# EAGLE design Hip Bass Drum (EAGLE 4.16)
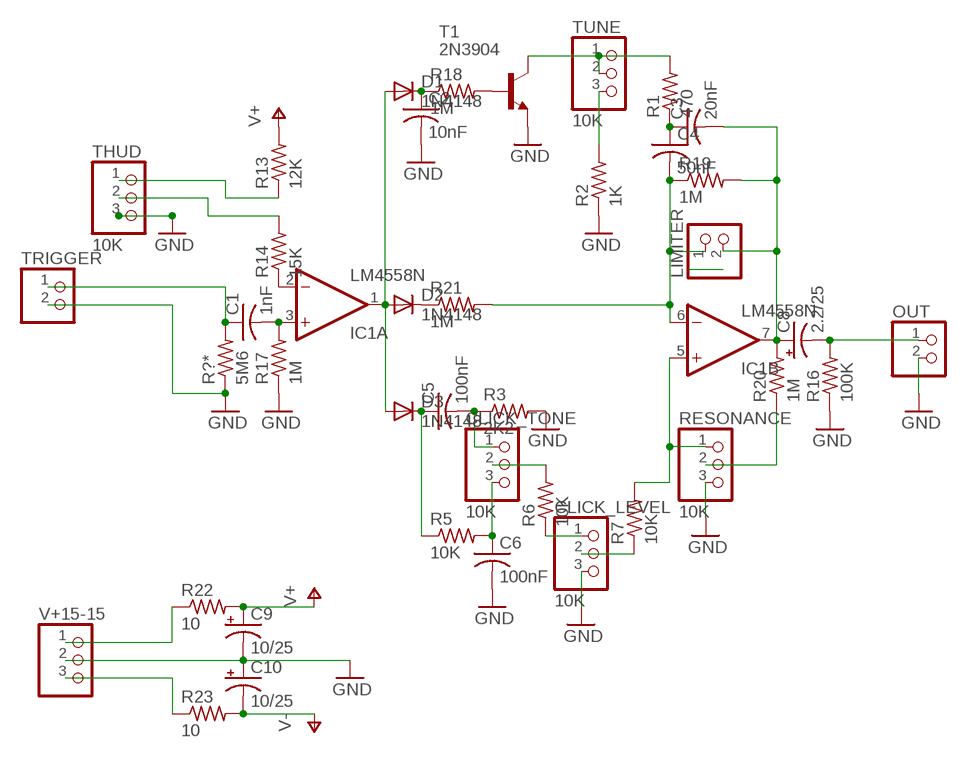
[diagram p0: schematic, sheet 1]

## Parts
C1  1nF  C-US025-030X050  [C025-030X050]
C2  10nF  C-US025-030X050  [C025-030X050]
C3  20nF  C-US025-030X050  [C025-030X050]
C4  50nF  C-US025-030X050  [C025-030X050]
C5  100nF  C-US025-030X050  [C025-030X050]
C6  100nF  C-US025-030X050  [C025-030X050]
C8  2.2/25  CPOL-USE2.5-7  [E2,5-7]
C9  10/25  CPOL-USE2.5-7  [E2,5-7]
C10  10/25  CPOL-USE2.5-7  [E2,5-7]
CLICK_LEVEL  10K  PINHD-1X3  [1X03]
CLICK_TONE  10K  PINHD-1X3  [1X03]
D1  1N4148  [DO35-10]
D2  1N4148  [DO35-10]
D3  1N4148  [DO35-10]
IC1  LM4558N  [DIL08]
LIMITER  PINHD-1X2  [1X02]
OUT  PINHD-1X2  [1X02]
R1  470  R-US_0207/10  [0207/10]
R2  1K  R-US_0207/10  [0207/10]
R3  2K2  R-US_0207/10  [0207/10]
R5  10K  R-US_0207/10  [0207/10]
R6  10K  R-US_0207/10  [0207/10]
R7  10K  R-US_0207/10  [0207/10]
R13  12K  R-US_0207/10  [0207/10]
R14  15K  R-US_0207/10  [0207/10]
R16  100K  R-US_0207/10  [0207/10]
R17  1M  R-US_0207/10  [0207/10]
R18  1M  R-US_0207/10  [0207/10]
R19  1M  R-US_0207/10  [0207/10]
R20  1M  R-US_0207/10  [0207/10]
R21  1M  R-US_0207/10  [0207/10]
R22  10  R-US_0207/10  [0207/10]
R23  10  R-US_0207/10  [0207/10]
R?*  5M6  R-US_0207/10  [0207/10]
RESONANCE  10K  PINHD-1X3  [1X03]
T1  2N3904  [TO92]
THUD  10K  PINHD-1X3  [1X03]
TRIGGER  PINHD-1X2  [1X02]
TUNE  10K  PINHD-1X3  [1X03]
V+15-15  PINHD-1X3  [1X03]

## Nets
GND: C2.2 C6.2 C9.- C10.+ CLICK_LEVEL.3 OUT.2 R2.1 R3.2 R16.1 R17.1 R?*.1 RESONANCE.3 T1.3(E) THUD.3 TRIGGER.2 V+15-15.2
N$1: C1.2 IC1.3(A:+IN) R17.2
N$2: C1.1 R?*.2 TRIGGER.1
N$3: IC1.2(A:-IN) R14.1
N$4: R22.1 V+15-15.1
N$5: R23.1 V+15-15.3
N$6: R13.1 THUD.1
N$7: R14.2 THUD.2
N$8: C2.1 D1.C R18.1
N$9: R18.2 T1.2(B)
N$10: D1.A D2.A D3.A IC1.1(A:OUT)
N$11: R1.2 T1.1(C) TUNE.1 TUNE.2
N$12: R2.2 TUNE.3
N$13: C3.1 C4.1 R1.1
N$14: C4.2 IC1.6(B:-IN) LIMITER.1 R19.1 R21.2
N$15: C3.2 C8.+ IC1.7(B:OUT) LIMITER.2 R19.2 R20.2
N$16: D2.C R21.1
N$17: C8.- OUT.1 R16.2
N$18: IC1.5(B:+IN) R7.2 RESONANCE.1
N$19: R20.1 RESONANCE.2
N$20: C5.1 D3.C R5.1
N$21: C6.1 CLICK_TONE.3 R5.2
N$22: C5.2 CLICK_TONE.1 R3.1
N$23: CLICK_TONE.2 R6.2
N$24: CLICK_LEVEL.1 R6.1
N$25: CLICK_LEVEL.2 R7.1
V+: C9.+ R13.2 R22.2
V-: C10.- R23.2

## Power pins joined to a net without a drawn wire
V+: IC1.8(P:V+)
V-: IC1.4(P:V-)

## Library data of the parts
C1-C6 = rcl:C-US: CAPACITOR, American symbol
C8-C10 = rcl:CPOL-US: POLARIZED CAPACITOR, American symbol
CLICK_LEVEL CLICK_TONE RESONANCE THUD TUNE V+15-15 = pinhead:PINHD-1X3: PIN HEADER
D1-D3 = diode:1N4148: DIODE
IC1 = linear:*4558: OP AMP
LIMITER OUT TRIGGER = pinhead:PINHD-1X2: PIN HEADER
R1-R3 R5-R7 R13 R14 R16-R23 R?* = rcl:R-US_: RESISTOR, American symbol
T1 = transistor:2N3904: NPN TRANSISTOR

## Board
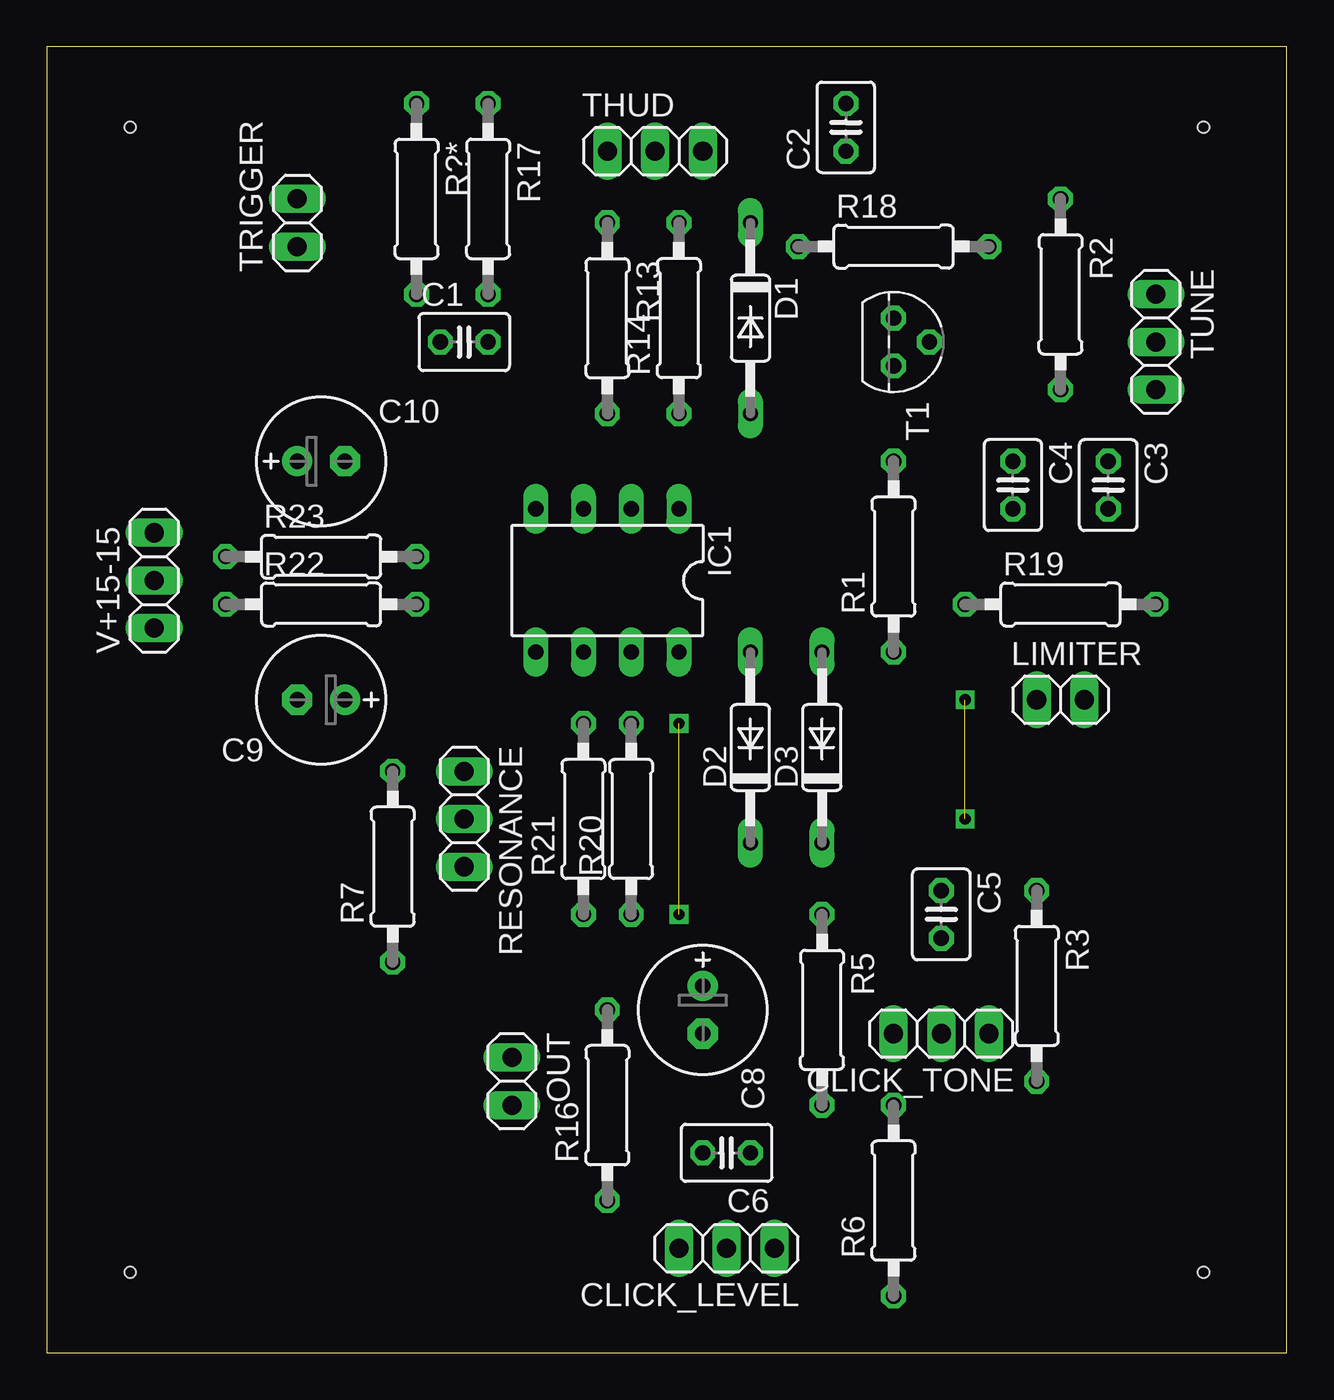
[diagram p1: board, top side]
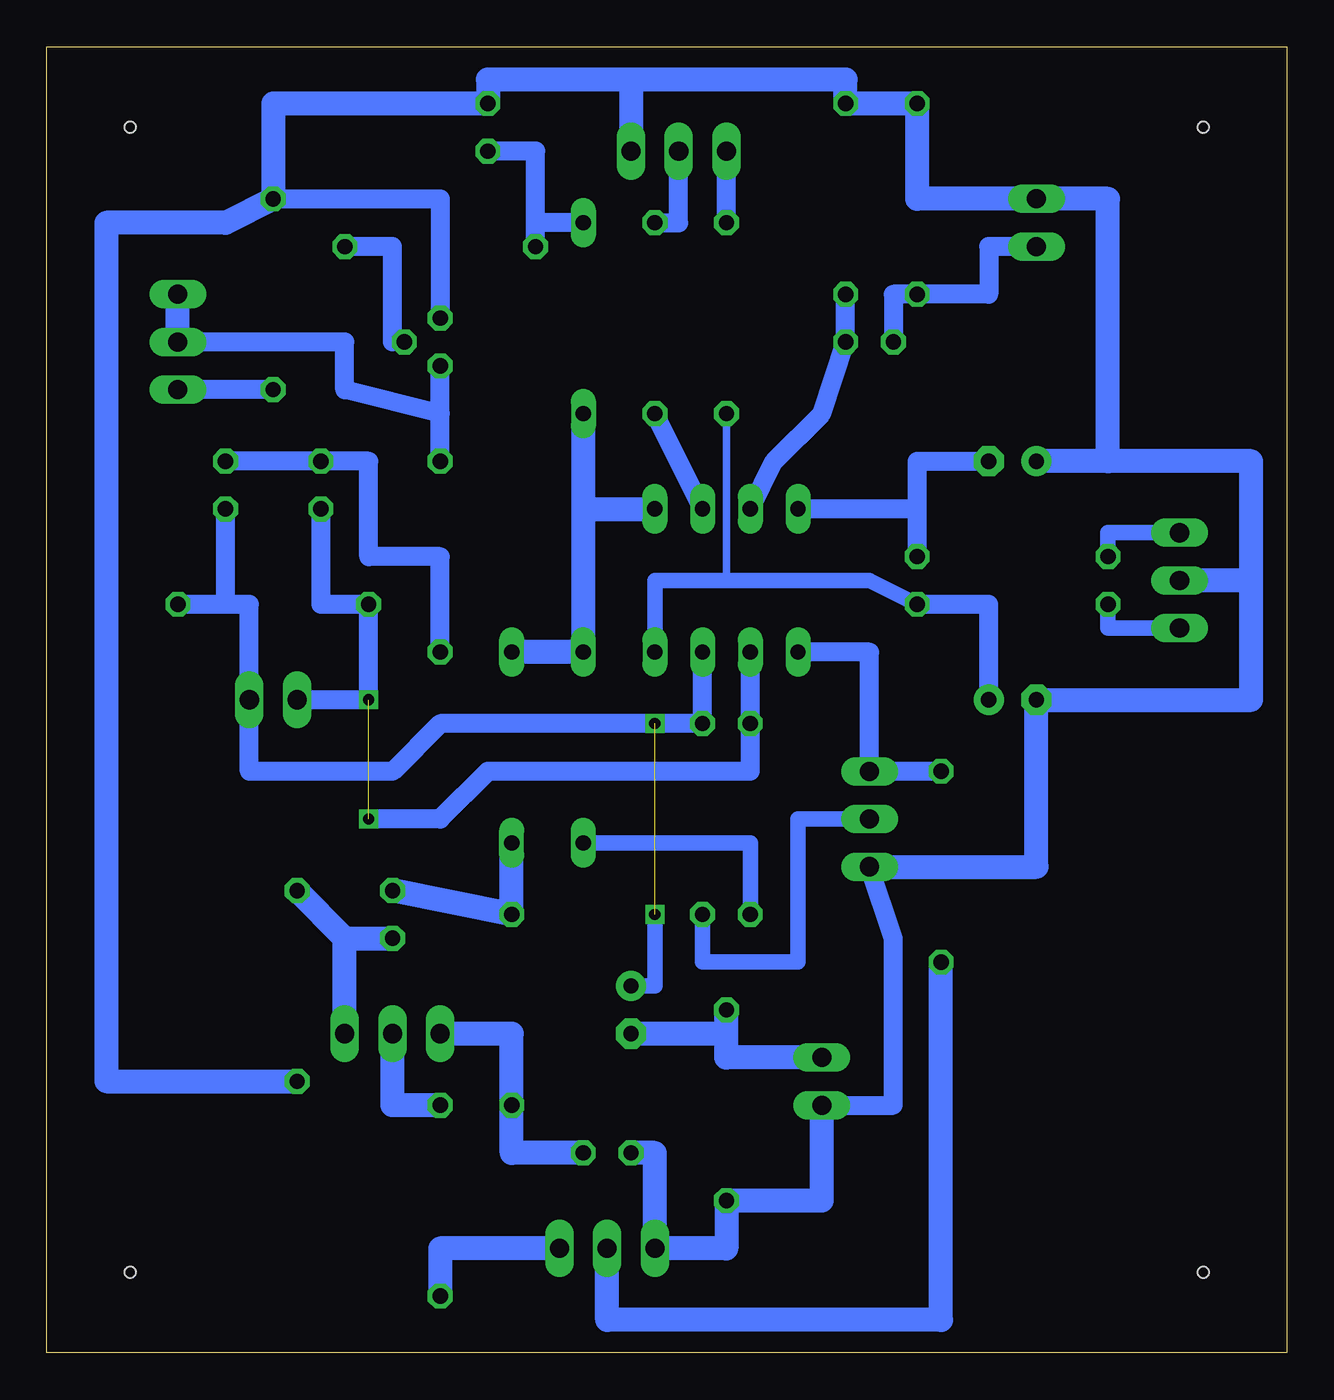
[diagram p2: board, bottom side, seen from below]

Size 66.02 x 69.52 mm. Coordinates in mm from the lower left corner, seen from the top.
Outline: 0,0 66.02,0 66.02,69.52 0,69.52 0,0
Copper layers (1*16): Top 0.035mm / dielectric 1.5mm / Bottom 0.035mm
Design rules "default": minimum track width 10mil, minimum drill 24mil, track to track 8mil, track to pad 8mil, pad to pad 8mil, via to via 8mil, smd to smd 8mil, copper to edge 40mil, drill to drill 8mil, minimum pad ring 10mil, minimum via ring 8mil, stop-mask expansion 4mil, vias tented up to drill 0mil, thermal gap 10mil
Holes 0.6 mm at 4.44,4.28 4.44,65.24 61.59,65.24 61.59,4.28

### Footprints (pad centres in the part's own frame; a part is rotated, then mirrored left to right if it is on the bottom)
C025-030X050 = drill 0.813 octagon: 1 -1.27,0; 2 1.27,0
E2,5-7 = drill 0.813 pad 1.6 round: + -1.27,0 | drill 0.813 pad 1.6 octagon: - 1.27,0
1X03 = drill 1.016 long: 1 -2.54,0; 2 0,0; 3 2.54,0
DO35-10 = drill 0.813 long: A 5.08,0; C -5.08,0
DIL08 = drill 0.813 long: 1 -3.81,-3.81; 2 -1.27,-3.81; 3 1.27,-3.81; 4 3.81,-3.81; 5 3.81,3.81; 6 1.27,3.81; 7 -1.27,3.81; 8 -3.81,3.81
1X02 = drill 1.016 long: 1 -1.27,0; 2 1.27,0
0207/10 = drill 0.813 octagon: 1 -5.08,0; 2 5.08,0
TO92 = drill 0.813 octagon: 1 1.27,0; 2 0,1.905; 3 -1.27,0

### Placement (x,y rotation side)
C1  22.22,53.81 0 top
C2  42.54,65.24 90 top
C3  56.51,46.19 270 top
C4  51.43,46.19 270 top
C5  47.62,23.33 270 top
C6  36.19,10.63 180 top
C8  34.92,18.25 270 top
C9  14.6,34.76 180 top
C10  14.6,47.46 0 top
CLICK_LEVEL  36.19,5.55 180 top
CLICK_TONE  47.62,16.98 180 top
D1  37.46,55.08 270 top
D2  37.46,32.22 90 top
D3  41.27,32.22 90 top
IC1  29.84,41.11 180 top
LIMITER  53.97,34.76 0 top
OUT  24.76,14.44 270 top
R1  45.08,42.38 90 top
R2  53.97,56.35 270 top
R3  52.7,19.52 270 top
R5  41.27,18.25 270 top
R6  45.08,8.09 90 top
R7  18.41,25.87 90 top
R13  29.84,55.08 270 top
R14  33.65,55.08 90 top
R16  29.84,13.17 90 top
R17  23.49,61.43 270 top
R18  45.08,58.89 0 top
R19  53.97,39.84 0 top
R20  31.11,28.41 90 top
R21  28.57,28.41 90 top
R22  14.6,39.84 0 top
R23  14.6,42.38 0 top
R?*  19.68,61.43 270 top
RESONANCE  22.22,28.41 270 top
T1  45.08,53.81 270 top
THUD  32.38,63.97 0 top
TRIGGER  13.33,60.16 90 top
TUNE  59.05,53.81 270 top
V+15-15  5.71,41.11 90 top

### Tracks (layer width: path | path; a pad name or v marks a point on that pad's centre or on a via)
GND
  Bottom 1.016: R2.1 45.08,61.43 T1.3 | RESONANCE.3 20.95,22.06 20.95,13.17 OUT.2
  Bottom 1.27: 1.9,41.11 1.9,47.46 9.52,47.46 | 9.52,47.46 C10.+ | 9.52,47.46 9.52,61.43 TRIGGER.2 19.68,61.43 R?*.1 R17.1 23.49,67.78 34.92,67.78 | 34.92,67.78 42.54,67.78 C2.2 53.97,66.51 R2.1 56.51,60.16 62.86,60.16 62.86,14.44 R3.2 | 34.92,67.78 THUD.3 | 1.9,41.11 V+15-15.2 | 1.9,41.11 1.9,34.76 C9.- 13.33,25.87 RESONANCE.3 | OUT.2 24.76,8.09 R16.1 29.84,5.55 CLICK_LEVEL.3 33.65,10.63 C6.2
N$1
  Bottom 1.016: R17.2 C1.2 24.76,50 27.3,47.46 IC1.3
N$2
  Bottom 1.016: TRIGGER.1 15.87,58.89 15.87,56.35 R?*.2 20.95,56.35 C1.1
N$3
  Bottom 1.016: IC1.2 R14.1
N$4
  Bottom 0.813: V+15-15.1 9.52,38.57 R22.1
N$5
  Bottom 0.813: V+15-15.3 9.52,43.65 R23.1
N$6
  Bottom 1.016: R13.1 THUD.1
N$7
  Bottom 1.016: R14.2 32.38,60.16 THUD.2
N$8
  Bottom 0.406: 40,60.16 R18.1
  Bottom 1.016: D1.C 40,60.16 | R18.1 40,63.97 C2.1
N$9
  Bottom 0.406: T1.2 47.62,53.81
  Bottom 1.016: 47.62,53.81 47.62,58.89 R18.2
N$10
  Bottom 1.27: 37.46,44.92 D1.A | 37.46,44.92 IC1.1 | 37.46,44.92 D2.A D3.A
N$11
  Bottom 1.016: TUNE.2 50.16,53.81 50.16,51.27 45.08,50 | 45.08,50 T1.1 | R1.2 45.08,50
  Bottom 1.27: TUNE.2 TUNE.1
N$12
  Bottom 1.016: R2.2 TUNE.3
N$13
  Bottom 1.016: R1.1 45.08,42.38 48.89,42.38 48.89,47.46 C4.1 C3.1
N$14  (via drill 0.6)  (1 unrouted)
  Bottom 0.406: IC1.6 R21.2
  Bottom 1.016: C4.2 51.43,39.84 R19.1 v48.89,34.76 LIMITER.1 | IC1.6 28.57,30.95 42.54,30.95 45.08,28.41 48.89,28.41
N$15  (1 unrouted)
  Bottom 0.406: R19.2 56.51,39.84
  Bottom 0.813: C8.+ 33.65,19.52 33.65,23.33
  Bottom 1.016: IC1.7 R20.2 33.65,33.49 45.08,33.49 47.62,30.95 55.24,30.95 LIMITER.2 55.24,39.84 R19.2 | 56.51,39.84 C3.2
N$16
  Bottom 0.813: R21.1 28.57,27.14 D2.C
N$17
  Bottom 1.27: OUT.1 29.84,15.71 29.84,16.98 | 29.84,16.98 R16.2 | 29.84,16.98 C8.-
N$18
  Bottom 1.016: IC1.5 22.22,37.3 RESONANCE.1 R7.2
N$19
  Bottom 0.813: R20.1 31.11,20.79 26.03,20.79 26.03,28.41 RESONANCE.2
N$20
  Bottom 1.27: D3.C R5.1 C5.1
N$21
  Bottom 1.27: CLICK_TONE.3 41.27,16.98 R5.2 41.27,10.63 C6.1
N$22
  Bottom 1.27: 50.16,22.06 C5.2 | 50.16,22.06 R3.1 | CLICK_TONE.1 50.16,22.06
N$23
  Bottom 1.27: CLICK_TONE.2 47.62,13.17 R6.2
N$24
  Bottom 1.27: CLICK_LEVEL.1 45.08,5.55 R6.1
N$25
  Bottom 1.27: R7.1 18.41,1.74 36.19,1.74 CLICK_LEVEL.2
N$26  (via drill 0.6)
  other vias: 33.65,33.49
N$27  (via drill 0.6)
  other vias: 33.65,23.33
N$28  (via drill 0.6)
  other vias: 48.89,28.41
V+
  Bottom 0.406: 29.84,41.11 R13.2
  Bottom 0.813: R22.2 22.22,41.11 29.84,41.11 33.65,41.11 IC1.8
  Bottom 1.016: R22.2 15.87,39.84 C9.+
V-
  Bottom 1.016: C10.- 19.68,47.46 19.68,44.92 | R23.2 19.68,44.92 | 19.68,44.92 IC1.4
